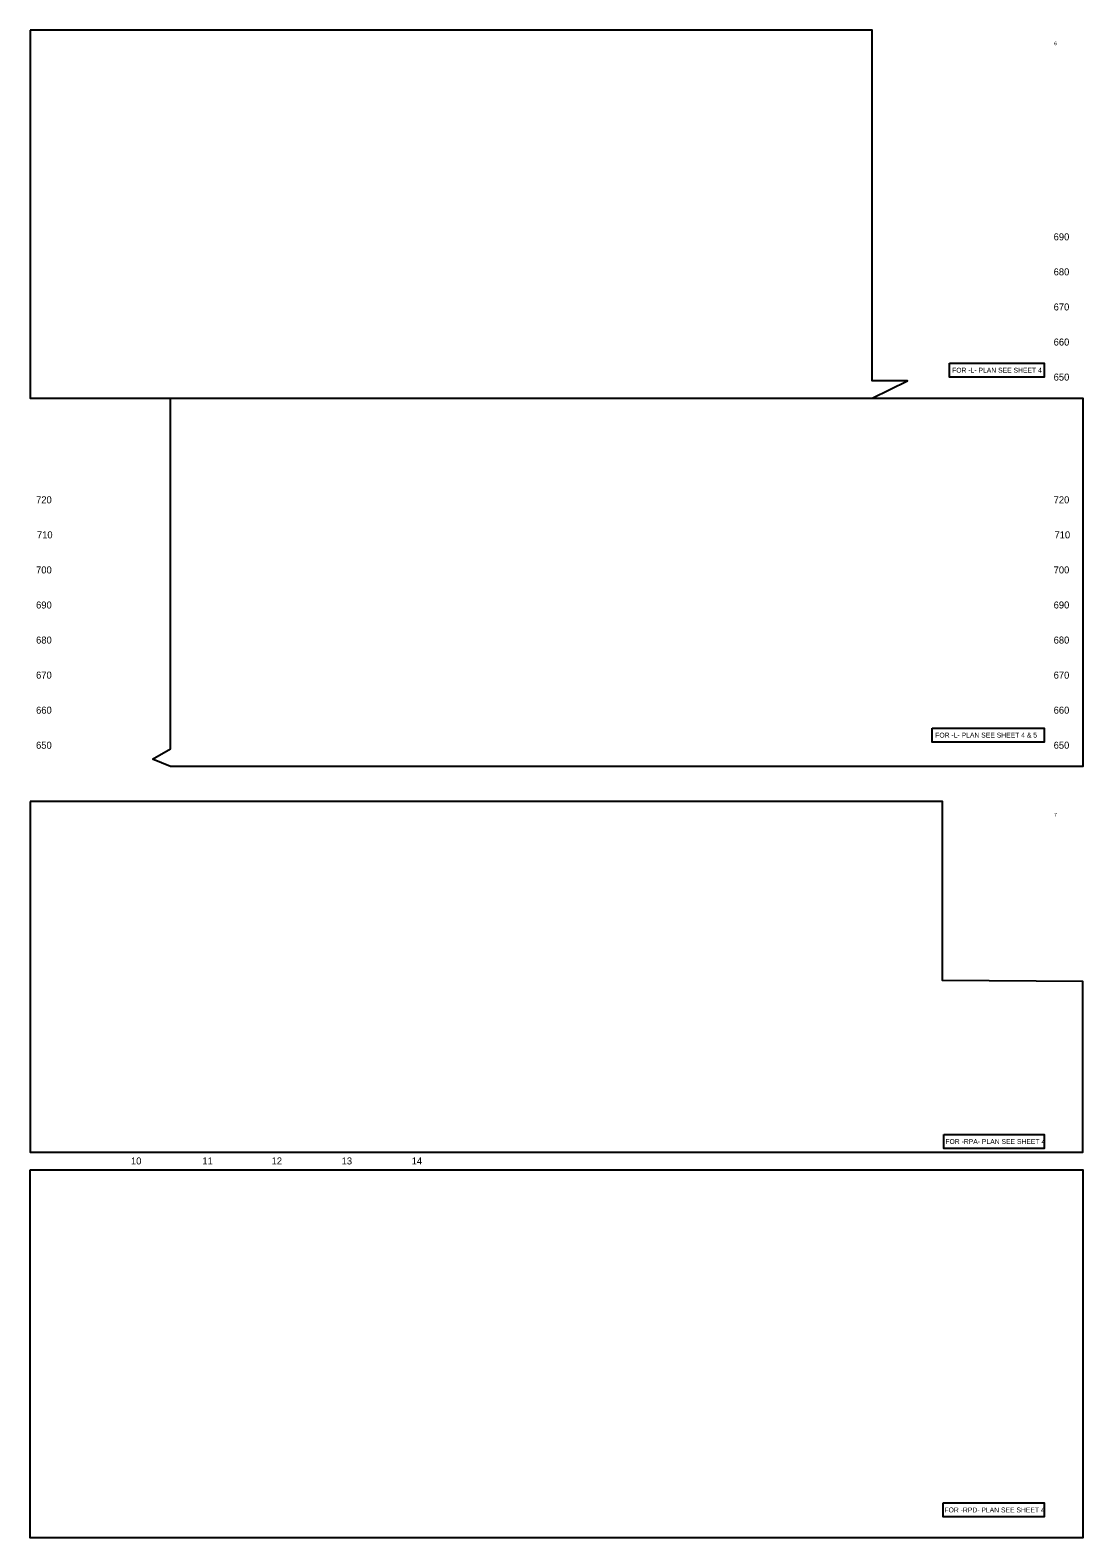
# Model space of a CAD drawing. Extents: x 2472548 to 2478566, y 619381 to 625389.
# Drawn here: x 2474228 to 2475728, y 619381 to 621531 of the extents above; entities that cross this region are included whole.
import ezdxf

# ---------------------------------------------------------------- set-up
doc = ezdxf.new("R2010")
doc.units = 0
for name, color, linetype in [('ENG SEALS CELL', 7, 'Continuous'), ('Old_Level_2', 7, 'Continuous'), ('Prop Grid Mask', 7, 'Continuous'), ('Scratch_Level_0', 7, 'Continuous'), ('Scratch_Level_3', 7, 'Continuous'), ('Sheet PE Seal Cell', 7, 'Continuous')]:
    doc.layers.add(name, color=color, linetype=linetype)

msp = doc.modelspace()

# ---------------------------------------------------------------- linework, layer by layer
at = {"layer": 'ENG SEALS CELL'}
for points in [[(2474227.9, 621531.1), (2474227.9, 621006.1), (2475427.9, 621006.1), (2475477.9, 621031.1), (2475427.9, 621031.1), (2475427.9, 621031.1), (2475427.9, 621531.1), (2475427.9, 621531.1)], [(2474227.9, 621531.1), (2474227.9, 621006.1), (2475427.9, 621006.1), (2475477.9, 621031.1), (2475427.9, 621031.1), (2475427.9, 621031.1), (2475427.9, 621531.1), (2475427.9, 621531.1)], [(2474402.2, 620491.5), (2474427.9, 620506.1), (2474427.9, 621006.1), (2475727.9, 621006.1), (2475727.9, 620481.1), (2474427.9, 620481.1)], [(2474227.9, 620431.1), (2474227.9, 619931.1), (2475727.9, 619931.1), (2475727.9, 620174.5), (2475527.9, 620176.1), (2475527.9, 620431.1)], [(2474227.9, 619906.1), (2475727.9, 619906.1), (2475727.9, 619381.1), (2474227.9, 619381.1)]]:
    msp.add_lwpolyline(points, close=True, dxfattribs=at)
at = {"layer": 'Prop Grid Mask'}
for points in [[(2475538, 621056.4), (2475672.6, 621056.4), (2475672.6, 621036.3), (2475538, 621036.3)], [(2475513.1, 620535.9), (2475672.6, 620535.9), (2475672.6, 620515.8), (2475513.1, 620515.8)], [(2475529.8, 619956.5), (2475672.6, 619956.5), (2475672.6, 619936.3), (2475529.8, 619936.3)], [(2475528.7, 619431.1), (2475672.6, 619431.1), (2475672.6, 619411), (2475528.7, 619411)]]:
    msp.add_lwpolyline(points, close=True, dxfattribs=at)

# ---------------------------------------------------------------- texts
at = {"layer": 'Old_Level_2'}
for s, p in [('6', (2475687.1, 621509.7)), ('7', (2475687, 620409.7))]:
    msp.add_text(s, height=5, dxfattribs=at).set_placement(p)
at = {"layer": 'Scratch_Level_0'}
for s, p in [('FOR -L- PLAN SEE SHEET 4', (2475541.6, 621042.7)), ('FOR -L- PLAN SEE SHEET 4 & 5', (2475517.6, 620522.3)), ('FOR -RPA- PLAN SEE SHEET 4', (2475532, 619942.8)), ('FOR -RPD- PLAN SEE SHEET 4', (2475530.7, 619417.4))]:
    msp.add_text(s, height=7, dxfattribs=at).set_placement(p)
at = {"layer": 'Scratch_Level_3'}
for s, p in [('10', (2474371.5, 619913.6)), ('11', (2474473.3, 619913.6)), ('12', (2474571.9, 619913.6)), ('13', (2474671.7, 619913.6)), ('14', (2474771.5, 619913.6))]:
    msp.add_text(s, height=10, dxfattribs=at).set_placement(p)
at = {"layer": 'Sheet PE Seal Cell'}
for s, p in [('690', (2475686.3, 621231.4)), ('680', (2475686.3, 621181.4)), ('670', (2475686.3, 621131.4)), ('660', (2475686.3, 621081.4)), ('650', (2475686.3, 621031.4)), ('720', (2474236.3, 620856.4)), ('720', (2475686.3, 620856.4)), ('710', (2474237.5, 620806.4)), ('710', (2475687.5, 620806.4)), ('700', (2474236.3, 620756.4)), ('700', (2475686.3, 620756.4)), ('690', (2474236.3, 620706.4)), ('690', (2475686.3, 620706.4)), ('680', (2474236.3, 620656.4)), ('680', (2475686.3, 620656.4)), ('670', (2474236.3, 620606.4)), ('670', (2475686.3, 620606.4)), ('660', (2474236.3, 620556.4)), ('660', (2475686.3, 620556.4)), ('650', (2474236.3, 620506.4)), ('650', (2475686.3, 620506.4))]:
    msp.add_text(s, height=10, dxfattribs=at).set_placement(p)

doc.saveas('drawing.dxf')
